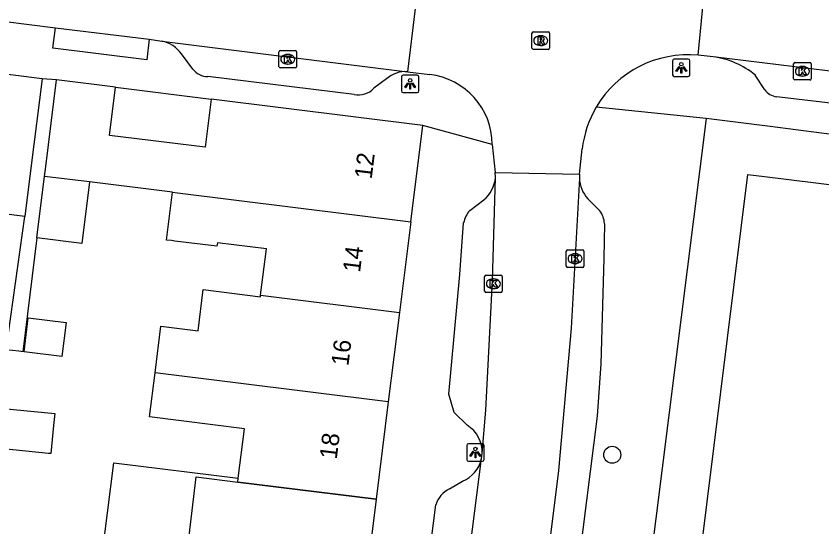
# Model space of a CAD drawing. Extents: x 161696 to 162377, y 380761 to 381673.
# Drawn here: x 162094.67 to 162140.85, y 381365.02 to 381394.29 of the extents above; entities that cross this region are included whole.
import ezdxf

# ---------------------------------------------------------------- set-up
doc = ezdxf.new("R2010")
doc.units = 0
for name, color, linetype in [('IMGEO_Boom', 7, 'Continuous'), ('IMGEO_Kolk', 7, 'Continuous'), ('IMGEO_Lichtpunt', 7, 'Continuous'), ('IMGEO_Muur', 7, 'Continuous'), ('IMGEO_Pand', 7, 'Continuous'), ('IMGEO_Pand_nummerreeks', 7, 'Continuous'), ('IMGEO_Pand_vergunning_verleend', 7, 'Continuous'), ('IMGEO_Rijbaan_lokaal_open', 7, 'Continuous'), ('IMGEO_Rioolput', 7, 'Continuous'), ('IMGEO_Voetpad_open', 7, 'Continuous')]:
    doc.layers.add(name, color=color, linetype=linetype)

msp = doc.modelspace()

# ---------------------------------------------------------------- linework, layer by layer
at = {"layer": 'IMGEO_Boom'}
msp.add_circle((162128.84, 381369.156), 0.489, dxfattribs=at)
at = {"layer": 'IMGEO_Kolk'}
for p, q in [((162109.814, 381392.322), (162110.666, 381392.322)), ((162109.739, 381391.396), (162109.739, 381392.248)), ((162110.227, 381392.102), (162110.252, 381392.102)), ((162110.74, 381392.248), (162110.74, 381391.396)), ((162110.25, 381391.542), (162110.225, 381391.542)), ((162139.234, 381390.707), (162139.234, 381391.559)), ((162139.309, 381391.633), (162140.161, 381391.633)), ((162139.722, 381391.413), (162139.747, 381391.413)), ((162140.235, 381391.559), (162140.235, 381390.707)), ((162110.666, 381391.322), (162109.814, 381391.322)), ((162140.161, 381390.633), (162139.309, 381390.633)), ((162139.745, 381390.853), (162139.72, 381390.853)), ((162126.205, 381379.967), (162126.205, 381380.819)), ((162126.28, 381380.893), (162127.132, 381380.893)), ((162127.206, 381380.819), (162127.206, 381379.967)), ((162126.693, 381380.673), (162126.718, 381380.673)), ((162127.132, 381379.893), (162126.28, 381379.893)), ((162126.716, 381380.113), (162126.691, 381380.113)), ((162121.524, 381378.528), (162121.524, 381379.38)), ((162121.599, 381379.454), (162122.451, 381379.454)), ((162122.525, 381379.38), (162122.525, 381378.528)), ((162122.012, 381379.234), (162122.037, 381379.234)), ((162122.451, 381378.454), (162121.599, 381378.454)), ((162122.035, 381378.674), (162122.01, 381378.674))]:
    msp.add_line(p, q, dxfattribs=at)
for points in [[(162109.814, 381392.322), (162110.666, 381392.322)], [(162109.739, 381391.396), (162109.739, 381392.248)], [(162110.06, 381392.022), (162110.183, 381392.022), (162110.183, 381391.871), (162110.313, 381392.022), (162110.477, 381392.022), (162110.331, 381391.871), (162110.484, 381391.622), (162110.332, 381391.622), (162110.247, 381391.786), (162110.183, 381391.719), (162110.183, 381391.622), (162110.06, 381391.622), (162110.06, 381392.022)], [(162110.74, 381392.248), (162110.74, 381391.396)], [(162139.234, 381390.707), (162139.234, 381391.559)], [(162139.309, 381391.633), (162140.161, 381391.633)], [(162140.235, 381391.559), (162140.235, 381390.707)], [(162110.666, 381391.322), (162109.814, 381391.322)], [(162139.555, 381391.333), (162139.678, 381391.333), (162139.678, 381391.182), (162139.808, 381391.333), (162139.972, 381391.333), (162139.826, 381391.182), (162139.979, 381390.933), (162139.827, 381390.933), (162139.742, 381391.097), (162139.678, 381391.03), (162139.678, 381390.933), (162139.555, 381390.933), (162139.555, 381391.333)], [(162140.161, 381390.633), (162139.309, 381390.633)], [(162126.205, 381379.967), (162126.205, 381380.819)], [(162126.28, 381380.893), (162127.132, 381380.893)], [(162127.206, 381380.819), (162127.206, 381379.967)], [(162126.526, 381380.593), (162126.649, 381380.593), (162126.649, 381380.442), (162126.779, 381380.593), (162126.943, 381380.593), (162126.797, 381380.442), (162126.95, 381380.193), (162126.798, 381380.193), (162126.713, 381380.357), (162126.649, 381380.29), (162126.649, 381380.193), (162126.526, 381380.193), (162126.526, 381380.593)], [(162127.132, 381379.893), (162126.28, 381379.893)], [(162121.524, 381378.528), (162121.524, 381379.38)], [(162121.599, 381379.454), (162122.451, 381379.454)], [(162122.525, 381379.38), (162122.525, 381378.528)], [(162121.845, 381379.154), (162121.968, 381379.154), (162121.968, 381379.003), (162122.098, 381379.154), (162122.262, 381379.154), (162122.116, 381379.003), (162122.269, 381378.754), (162122.117, 381378.754), (162122.032, 381378.918), (162121.968, 381378.851), (162121.968, 381378.754), (162121.845, 381378.754), (162121.845, 381379.154)], [(162122.451, 381378.454), (162121.599, 381378.454)]]:
    msp.add_lwpolyline(points, dxfattribs=at)
for centre, start, end in [((162109.816, 381392.246), 91.552, 178.448), ((162109.816, 381392.246), 91.552, 178.448), ((162110.664, 381392.246), 1.552, 88.448), ((162110.664, 381392.246), 1.552, 88.448), ((162109.816, 381391.398), 181.552, 268.448), ((162109.816, 381391.398), 181.552, 268.448), ((162110.664, 381391.398), 271.552, 358.448), ((162110.664, 381391.398), 271.552, 358.448), ((162139.311, 381391.557), 91.552, 178.448), ((162139.311, 381391.557), 91.552, 178.448), ((162140.159, 381391.557), 1.552, 88.448), ((162140.159, 381391.557), 1.552, 88.448), ((162139.311, 381390.709), 181.552, 268.448), ((162139.311, 381390.709), 181.552, 268.448), ((162140.159, 381390.709), 271.552, 358.448), ((162140.159, 381390.709), 271.552, 358.448), ((162126.282, 381380.817), 91.552, 178.448), ((162126.282, 381380.817), 91.552, 178.448), ((162127.13, 381380.817), 1.552, 88.448), ((162127.13, 381380.817), 1.552, 88.448), ((162126.282, 381379.969), 181.552, 268.448), ((162126.282, 381379.969), 181.552, 268.448), ((162127.13, 381379.969), 271.552, 358.448), ((162127.13, 381379.969), 271.552, 358.448), ((162121.601, 381379.378), 91.552, 178.448), ((162121.601, 381379.378), 91.552, 178.448), ((162122.449, 381379.378), 1.552, 88.448), ((162122.449, 381379.378), 1.552, 88.448), ((162121.601, 381378.53), 181.552, 268.448), ((162121.601, 381378.53), 181.552, 268.448), ((162122.449, 381378.53), 271.552, 358.448), ((162122.449, 381378.53), 271.552, 358.448)]:
    msp.add_arc(centre, 0.0765, start, end, dxfattribs=at)
for centre, major_axis, ratio, start_param, end_param in [((162110.226, 381391.822), (-0.387, 0.002), 0.722429, 4.712389, 7.853982), ((162110.251, 381391.822), (-0.39, 0.002), 0.717154, 1.570796, 4.712389), ((162139.721, 381391.133), (-0.387, 0.002), 0.722429, 4.712389, 7.853982), ((162139.746, 381391.133), (-0.39, 0.002), 0.717154, 1.570796, 4.712389), ((162126.692, 381380.393), (-0.387, 0.002), 0.722429, 4.712389, 7.853982), ((162126.717, 381380.393), (-0.39, 0.002), 0.717154, 1.570796, 4.712389), ((162122.011, 381378.954), (-0.387, 0.002), 0.722429, 4.712389, 7.853982), ((162122.036, 381378.954), (-0.39, 0.002), 0.717154, 1.570796, 4.712389)]:
    msp.add_ellipse(centre, major_axis=major_axis, ratio=ratio, start_param=start_param, end_param=end_param, dxfattribs=at)
at = {"layer": 'IMGEO_Lichtpunt'}
for p, q in [((162133.199, 381391.834), (162132.391, 381391.834)), ((162133.199, 381391.834), (162132.391, 381391.834)), ((162132.297, 381391.739), (162132.297, 381390.932)), ((162132.297, 381391.739), (162132.297, 381390.932)), ((162133.293, 381390.932), (162133.293, 381391.739)), ((162133.293, 381390.932), (162133.293, 381391.739)), ((162117.659, 381390.909), (162116.851, 381390.909)), ((162117.659, 381390.909), (162116.851, 381390.909)), ((162116.757, 381390.814), (162116.757, 381390.007)), ((162116.757, 381390.814), (162116.757, 381390.007)), ((162117.753, 381390.007), (162117.753, 381390.814)), ((162117.753, 381390.007), (162117.753, 381390.814)), ((162132.391, 381390.838), (162133.199, 381390.838)), ((162132.391, 381390.838), (162133.199, 381390.838)), ((162116.851, 381389.913), (162117.659, 381389.913)), ((162116.851, 381389.913), (162117.659, 381389.913)), ((162120.498, 381369.688), (162120.498, 381368.881)), ((162120.498, 381369.688), (162120.498, 381368.881)), ((162121.4, 381369.783), (162120.592, 381369.783)), ((162121.4, 381369.783), (162120.592, 381369.783)), ((162121.494, 381368.881), (162121.494, 381369.688)), ((162121.494, 381368.881), (162121.494, 381369.688)), ((162120.592, 381368.787), (162121.4, 381368.787)), ((162120.592, 381368.787), (162121.4, 381368.787))]:
    msp.add_line(p, q, dxfattribs=at)
for points in [[(162132.671, 381391.403), (162132.71, 381391.375), (162132.522, 381391.113), (162132.484, 381391.14), (162132.671, 381391.403)], [(162132.773, 381391.355), (162132.82, 381391.355), (162132.82, 381391.033), (162132.773, 381391.033), (162132.773, 381391.355)], [(162132.883, 381391.375), (162132.921, 381391.402), (162133.108, 381391.14), (162133.069, 381391.112), (162132.883, 381391.375)], [(162117.131, 381390.478), (162117.17, 381390.45), (162116.982, 381390.188), (162116.944, 381390.215), (162117.131, 381390.478)], [(162117.233, 381390.43), (162117.28, 381390.43), (162117.28, 381390.108), (162117.233, 381390.108), (162117.233, 381390.43)], [(162117.343, 381390.45), (162117.381, 381390.477), (162117.568, 381390.215), (162117.529, 381390.187), (162117.343, 381390.45)], [(162120.872, 381369.352), (162120.911, 381369.324), (162120.723, 381369.062), (162120.685, 381369.089), (162120.872, 381369.352)], [(162120.974, 381369.304), (162121.021, 381369.304), (162121.021, 381368.982), (162120.974, 381368.982), (162120.974, 381369.304)], [(162121.084, 381369.324), (162121.122, 381369.351), (162121.309, 381369.089), (162121.27, 381369.061), (162121.084, 381369.324)]]:
    msp.add_lwpolyline(points, dxfattribs=at)
for centre in [(162132.796, 381391.537), (162117.256, 381390.612), (162120.997, 381369.486)]:
    msp.add_circle(centre, 0.0994, dxfattribs=at)
for centre, start, end in [((162132.391, 381391.739), 90, 180), ((162132.391, 381391.739), 90, 180), ((162133.199, 381391.739), 0, 90), ((162133.199, 381391.739), 0, 90), ((162116.851, 381390.814), 90, 180), ((162116.851, 381390.814), 90, 180), ((162117.659, 381390.814), 0, 90), ((162117.659, 381390.814), 0, 90), ((162132.391, 381390.932), 180, 270), ((162132.391, 381390.932), 180, 270), ((162133.199, 381390.932), 270, 0), ((162133.199, 381390.932), 270, 360), ((162116.851, 381390.007), 180, 270), ((162116.851, 381390.007), 180, 270), ((162117.659, 381390.007), 270, 0), ((162117.659, 381390.007), 270, 360), ((162120.592, 381369.688), 90, 180), ((162120.592, 381369.688), 90, 180), ((162121.4, 381369.688), 0, 90), ((162121.4, 381369.688), 0, 90), ((162120.592, 381368.881), 180, 270), ((162120.592, 381368.881), 180, 270), ((162121.4, 381368.881), 270, 0), ((162121.4, 381368.881), 270, 360)]:
    msp.add_arc(centre, 0.0946, start, end, dxfattribs=at)
at = {"layer": 'IMGEO_Muur'}
msp.add_lwpolyline([(162100.377, 381390.217), (162105.852, 381389.539)], dxfattribs=at)
at = {"layer": 'IMGEO_Pand'}
for points in [[(162096.159, 381390.703), (162091.014, 381391.346)], [(162096.159, 381390.703), (162095.539, 381385.742), (162095.173, 381382.813)], [(162096.298, 381385.11), (162096.369, 381385.68), (162096.989, 381390.641)], [(162100.377, 381390.217), (162096.989, 381390.641)], [(162105.852, 381389.539), (162105.508, 381386.781), (162100.033, 381387.459), (162100.377, 381390.217)], [(162117.976, 381388.023), (162105.852, 381389.539)], [(162117.287, 381382.495), (162117.976, 381388.023)], [(162095.86, 381381.582), (162095.957, 381382.38), (162096.298, 381385.11)], [(162098.874, 381384.789), (162096.298, 381385.11)], [(162131.982, 381347.932), (162132.353, 381350.918), (162136.618, 381385.223), (162137.56, 381385.107), (162140.498, 381384.744), (162152.097, 381383.312), (162150.707, 381372.093), (162147.104, 381372.539), (162146.102, 381364.353), (162144.484, 381364.551), (162142.531, 381349.53), (162154.36, 381348.077), (162154.335, 381347.878), (162158.194, 381347.428), (162158.218, 381347.626), (162165.679, 381346.706), (162161.625, 381313.867), (162134.432, 381317.237), (162134.819, 381320.363), (162133.628, 381320.511), (162135.685, 381337.52), (162136.549, 381337.414), (162136.871, 381340.077), (162131.095, 381340.794)], [(162098.874, 381384.789), (162098.434, 381381.261), (162095.86, 381381.582)], [(162103.629, 381384.197), (162098.874, 381384.789)], [(162108.685, 381378.302), (162109.017, 381380.96), (162106.212, 381381.31), (162106.185, 381381.101), (162103.766, 381381.403), (162103.58, 381381.427), (162103.287, 381381.463), (162103.629, 381384.197)], [(162103.629, 381384.197), (162103.922, 381384.16), (162117.287, 381382.495)], [(162095.173, 381382.813), (162092.436, 381383.155), (162091.941, 381379.198), (162091.666, 381379.232)], [(162117.287, 381382.495), (162116.64, 381377.311)], [(162102.635, 381373.857), (162102.969, 381376.531), (162105.101, 381376.264), (162105.395, 381378.617), (162108.673, 381378.208), (162108.685, 381378.302)], [(162108.685, 381378.302), (162116.64, 381377.311)], [(162116.64, 381377.311), (162116.001, 381372.191)], [(162095.366, 381377.008), (162097.539, 381376.743), (162097.3, 381374.786), (162095.127, 381375.052), (162095.366, 381377.008)], [(162107.405, 381367.815), (162107.758, 381370.645), (162102.318, 381371.325), (162102.635, 381373.857)], [(162116.001, 381372.191), (162102.635, 381373.857)], [(162116.001, 381372.191), (162115.304, 381366.602)], [(162096.886, 381371.529), (162096.852, 381371.178), (162096.818, 381370.826), (162096.663, 381369.223), (162096.528, 381369.236), (162093.712, 381369.509), (162093.92, 381371.655), (162093.935, 381371.815), (162096.886, 381371.529)], [(162098.464, 381354.37), (162100.281, 381368.692), (162107.405, 381367.815)], [(162115.304, 381366.602), (162107.377, 381367.591), (162107.405, 381367.815)], [(162115.304, 381366.602), (162113.205, 381349.768)]]:
    msp.add_lwpolyline(points, dxfattribs=at)
at = {"layer": 'IMGEO_Pand_vergunning_verleend'}
msp.add_lwpolyline([(162098.123, 381351.682), (162098.464, 381354.37), (162098.635, 381355.714), (162103.467, 381355.034), (162104.996, 381367.883), (162107.377, 381367.591), (162115.304, 381366.602), (162113.205, 381349.768), (162098.123, 381351.682)], dxfattribs=at)
at = {"layer": 'IMGEO_Rijbaan_lokaal_open'}
for points in [[(162133.762, 381392.05), (162134.204, 381396.604)], [(162117.547, 381394.722), (162117.108, 381391.108)], [(162093.918, 381394.013), (162096.927, 381393.631)], [(162096.927, 381393.631), (162102.301, 381392.98)], [(162102.301, 381392.98), (162103.028, 381392.865)], [(162103.028, 381392.865), (162117.108, 381391.108)], [(162134.619, 381391.965), (162133.762, 381392.05)], [(162175.935, 381386.867), (162160.895, 381388.723), (162147.727, 381390.348), (162134.619, 381391.965)], [(162117.108, 381391.108), (162118.375, 381390.943)], [(162134.218, 381388.422), (162127.915, 381389.07)], [(162134.218, 381388.422), (162129.541, 381351.238), (162129.168, 381348.272)], [(162121.957, 381386.942), (162122.125, 381385.33)], [(162126.96, 381385.231), (162127.114, 381386.681)], [(162121.385, 381369.22), (162121.593, 381371.707), (162121.97, 381379.147), (162122.142, 381385.047)], [(162122.125, 381385.33), (162126.96, 381385.231)], [(162122.142, 381385.047), (162122.125, 381385.33)], [(162126.957, 381385.01), (162126.489, 381376.416), (162125.753, 381368.256), (162122.434, 381341.635)], [(162126.96, 381385.231), (162126.957, 381385.01)], [(162127.433, 381383.821), (162128.128, 381383.13)], [(162128.39, 381382.399), (162128.362, 381380.401), (162128.193, 381374.361), (162127.965, 381371.368), (162124.523, 381344.023)], [(162121.35, 381368.946), (162121.385, 381369.22)], [(162117.967, 381342.388), (162121.35, 381368.946)]]:
    msp.add_lwpolyline(points, dxfattribs=at)
for centre, radius, start, end in [((162133.174, 381385.978), 6.101, 84.4683, 149.5442), ((162117.917, 381386.929), 4.04, 0.1784, 83.4963), ((162133.186, 381385.974), 6.113, 149.5707, 173.3581), ((162128.894, 381385.096), 1.939, 182.5298, 221.1062), ((162127.09, 381382.346), 1.301, 2.3522, 37.0844)]:
    msp.add_arc(centre, radius, start, end, dxfattribs=at)
at = {"layer": 'IMGEO_Rioolput'}
for p, q in [((162124.237, 381392.464), (162124.237, 381393.316)), ((162124.312, 381393.39), (162125.164, 381393.39)), ((162125.238, 381393.316), (162125.238, 381392.464)), ((162124.725, 381393.17), (162124.75, 381393.17)), ((162125.164, 381392.39), (162124.312, 381392.39)), ((162124.748, 381392.61), (162124.723, 381392.61))]:
    msp.add_line(p, q, dxfattribs=at)
for points in [[(162124.237, 381392.464), (162124.237, 381393.316)], [(162124.312, 381393.39), (162125.164, 381393.39)], [(162125.238, 381393.316), (162125.238, 381392.464)], [(162124.826, 381393.088), (162124.574, 381393.09), (162124.574, 381392.69)], [(162124.574, 381392.69), (162124.698, 381392.69), (162124.698, 381392.852), (162124.709, 381392.852)], [(162124.752, 381393.009), (162124.698, 381393.009), (162124.698, 381392.928)], [(162124.698, 381392.928), (162124.75, 381392.928)], [(162124.756, 381392.823), (162124.827, 381392.69), (162124.967, 381392.69), (162124.902, 381392.816)], [(162125.164, 381392.39), (162124.312, 381392.39)]]:
    msp.add_lwpolyline(points, dxfattribs=at)
for centre, radius, start, end in [((162124.314, 381393.314), 0.0765, 91.552, 178.448), ((162124.314, 381393.314), 0.0765, 91.552, 178.448), ((162125.162, 381393.314), 0.0765, 1.552, 88.448), ((162125.162, 381393.314), 0.0765, 1.552, 88.448), ((162124.708, 381392.799), 0.0533, 26.0293, 88.6989), ((162124.734, 381393.117), 0.19, 274.7715, 282.9687), ((162124.758, 381392.913), 0.0964, 77.0061, 93.1865), ((162124.772, 381392.97), 0.0378, 276.6634, 79.6772), ((162124.825, 381392.978), 0.109, 350.3612, 89.416), ((162124.823, 381392.978), 0.112, 277.5842, 350.9817), ((162124.807, 381392.763), 0.108, 29.5134, 73.7905), ((162124.314, 381392.466), 0.0765, 181.552, 268.448), ((162124.314, 381392.466), 0.0765, 181.552, 268.448), ((162125.162, 381392.466), 0.0765, 271.552, 358.448), ((162125.162, 381392.466), 0.0765, 271.552, 358.448)]:
    msp.add_arc(centre, radius, start, end, dxfattribs=at)
for centre, major_axis, ratio, start_param, end_param in [((162124.724, 381392.89), (-0.387, 0.002), 0.722429, 4.712389, 7.853982), ((162124.749, 381392.89), (-0.39, 0.002), 0.717154, 1.570796, 4.712389)]:
    msp.add_ellipse(centre, major_axis=major_axis, ratio=ratio, start_param=start_param, end_param=end_param, dxfattribs=at)
at = {"layer": 'IMGEO_Voetpad_open'}
for points in [[(162102.301, 381392.98), (162102.155, 381391.786), (162096.783, 381392.465), (162096.927, 381393.631)], [(162104.808, 381391.25), (162104.152, 381392.127)], [(162137.575, 381390.07), (162137.039, 381390.91)], [(162096.989, 381390.641), (162096.159, 381390.703)], [(162114.05, 381389.796), (162105.655, 381390.825)], [(162115.909, 381390.698), (162115.177, 381390.156)], [(162100.377, 381390.217), (162105.852, 381389.539)], [(162147.201, 381388.62), (162138.252, 381389.676)], [(162227.307, 381376.913), (162226.777, 381376.984), (162226.745, 381376.844), (162140.834, 381387.594), (162137.883, 381387.964), (162134.218, 381388.422)], [(162121.957, 381386.942), (162117.976, 381388.023)], [(162120.673, 381383.156), (162121.475, 381383.76)], [(162095.86, 381381.582), (162095.063, 381375.06), (162094.826, 381375.089), (162094.098, 381375.165), (162095.173, 381382.813)], [(162120.521, 381370.845), (162119.772, 381371.568), (162119.479, 381372.621), (162120.112, 381379.487), (162120.32, 381382.44)], [(162119.507, 381367.201), (162120.255, 381367.647)], [(162116.125, 381345.875), (162118.732, 381366.287)]]:
    msp.add_lwpolyline(points, dxfattribs=at)
for centre, radius, start, end in [((162102.655, 381391.072), 1.831, 35.1755, 78.248), ((162133.984, 381387.204), 4.803, 50.4931, 82.3973), ((162105.667, 381391.906), 1.081, 217.3644, 269.3433), ((162116.971, 381389.552), 1.562, 84.9524, 132.804), ((162114.282, 381391.015), 1.241, 259.2462, 316.1841), ((162138.357, 381390.635), 0.964, 215.8421, 263.7609), ((162120.321, 381385.174), 1.826, 309.2115, 355.9967), ((162121.793, 381382.159), 1.499, 138.3145, 169.1973), ((162119.584, 381369.305), 1.803, 357.3078, 58.6907), ((162119.602, 381369.309), 1.785, 291.4591, 348.2821), ((162120.146, 381365.874), 1.473, 115.6975, 163.7119)]:
    msp.add_arc(centre, radius, start, end, dxfattribs=at)

# ---------------------------------------------------------------- texts
at = {"layer": 'IMGEO_Pand_nummerreeks'}
for s, p in [('12', (162115.049, 381384.924)), ('14', (162114.382, 381379.572)), ('16', (162113.714, 381374.217)), ('18', (162113.046, 381368.866))]:
    msp.add_text(s, height=1, rotation=82.8898, dxfattribs=at).set_placement(p)

doc.saveas('drawing.dxf')
